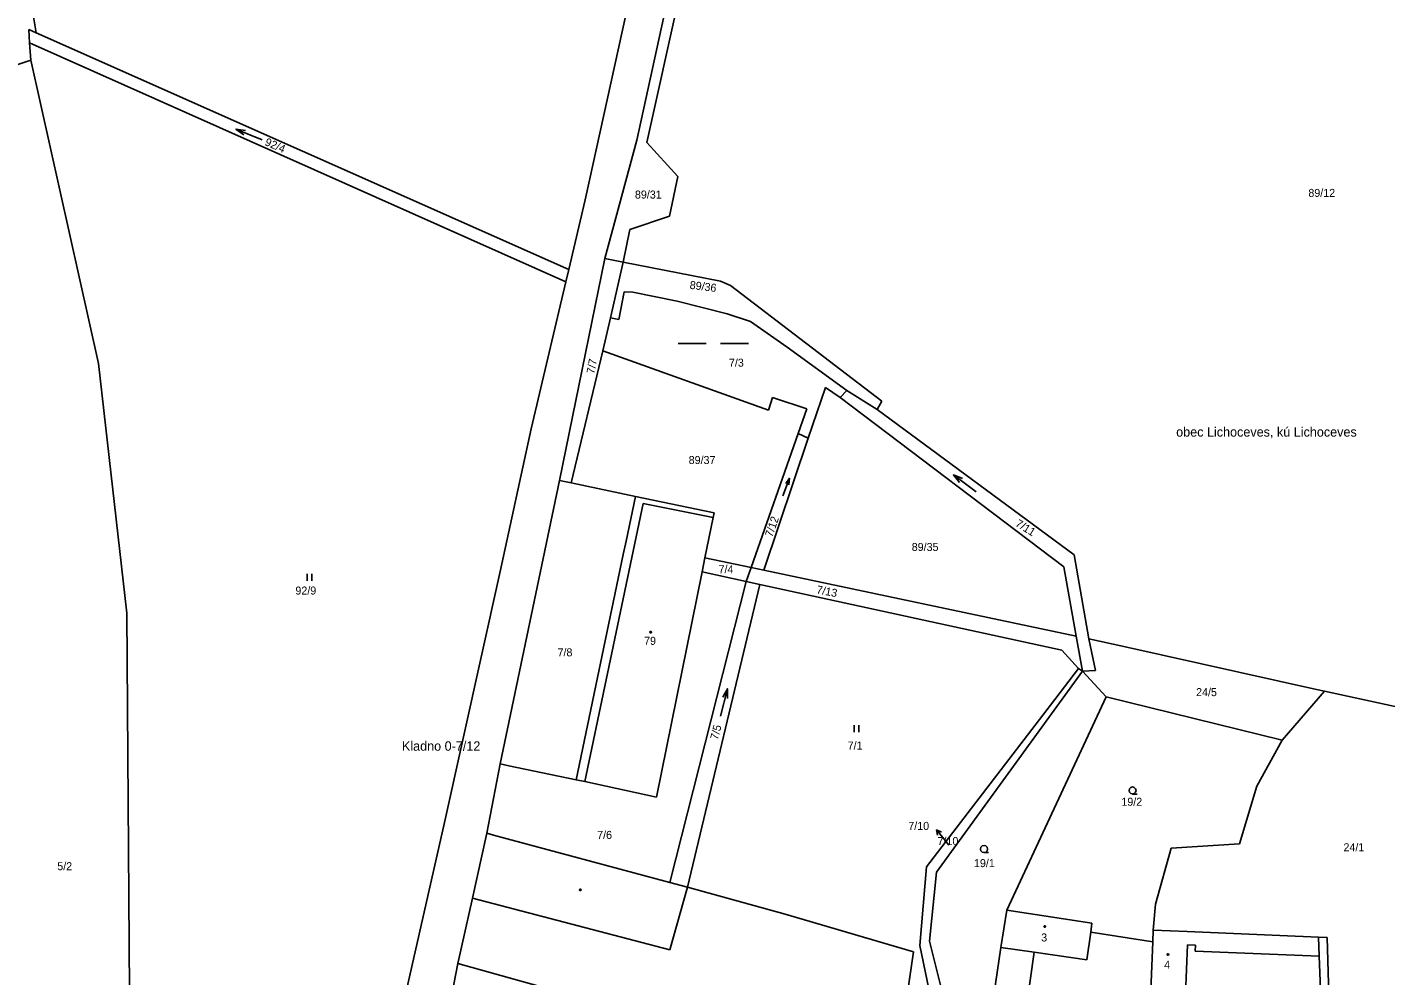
# Model space of a CAD drawing. Extents: x -752500 to -750336, y -1035826 to -1033500.
# Drawn here: x -751692 to -751403.4, y -1034303.4 to -1034101.8 of the extents above; entities that cross this region are included whole.
import ezdxf

# ---------------------------------------------------------------- set-up
doc = ezdxf.new("R2010")
doc.units = 0
for name, color, linetype in [('Default', 7, 'Continuous'), ('Hranice parcel', 7, 'Continuous'), ('ML1000', 7, 'Continuous'), ('Názevy ku_obce_kraje', 7, 'Continuous'), ('Parcelní čísla', 7, 'Continuous'), ('Pop  PČ popisy', 7, 'Continuous'), ('Vnitřní kresba', 7, 'Continuous'), ('Značky budov', 7, 'Continuous'), ('Značky kultur', 7, 'Continuous')]:
    doc.layers.add(name, color=color, linetype=linetype)

# ---------------------------------------------------------------- blocks, each defined once
blk = doc.blocks.new('304')
at = {"layer": 'Default'}
blk.add_lwpolyline([(0, 0), (-0.38, 0.1), (-0.65, 0.37), (-0.75, 0.74), (-0.65, 1.11), (-0.38, 1.38), (-0.01, 1.48), (0.36, 1.38), (0.63, 1.11), (0.73, 0.73), (0.63, 0.35), (0.36, 0.08), (-0.02, -0.02), (0.98, -0.02)], dxfattribs=at)
blk = doc.blocks.new('306')
at = {"layer": 'Default'}
for p, q in [((-0.5, 1.5), (-0.5, 0)), ((0.5, 0), (0.5, 1.5))]:
    blk.add_line(p, q, dxfattribs=at)
blk = doc.blocks.new('802')
at = {"layer": 'Default'}
blk.add_line((-3, 0), (3, 0), dxfattribs=at)
blk.add_lwpolyline([(1, 0.5), (3, 0), (1, -0.5)], dxfattribs=at)
blk = doc.blocks.new('803')
at = {"layer": 'Default'}
for p, q in [((-7.5, 0), (-1.5, 0)), ((1.5, 0), (7.5, 0))]:
    blk.add_line(p, q, dxfattribs=at)
blk = doc.blocks.new('10292')
at = {"layer": 'Default'}
blk.add_line((0, 3), (0, 0), dxfattribs=at)
blk.add_lwpolyline([(-0.5, 2), (0, 3), (0.5, 2)], dxfattribs=at)
blk = doc.blocks.new('402')
at = {"layer": 'Default'}
blk.add_lwpolyline([(0.09, 0.15), (0.18, 0), (0.09, -0.15), (-0.09, -0.15), (-0.18, 0), (-0.09, 0.15), (0.09, 0.15)], dxfattribs=at)

msp = doc.modelspace()

# ---------------------------------------------------------------- linework, layer by layer
at = {"layer": 'Hranice parcel'}
for p, q in [((-751532.72, -1033953.48), (-751573.48, -1034138.53)), ((-751700.05, -1034042.8), (-751690.1, -1034103.01)), ((-751562.48, -1034125.82), (-751545.42, -1034047.4)), ((-751543.07, -1034047.89), (-751560.38, -1034126.29)), ((-751691.65, -1034102.32), (-751691.51, -1034105.14)), ((-751691.65, -1034102.32), (-751690.1, -1034103.01)), ((-751690.1, -1034103.01), (-751576.97, -1034153.3)), ((-751691.51, -1034105.14), (-751577.59, -1034155.94)), ((-751691.51, -1034105.14), (-751691.23, -1034108.8)), ((-751691.23, -1034108.8), (-751714.32, -1034116.59)), ((-751691.23, -1034108.8), (-751676.86, -1034173.28)), ((-751569.32, -1034150.96), (-751562.48, -1034125.82)), ((-751560.38, -1034126.29), (-751553.8, -1034133.55)), ((-751555.58, -1034141.95), (-751553.8, -1034133.55)), ((-751576.97, -1034153.3), (-751573.48, -1034138.53)), ((-751563.96, -1034144.78), (-751555.58, -1034141.95)), ((-751565.42, -1034151.74), (-751563.96, -1034144.78)), ((-751569.32, -1034150.96), (-751578.92, -1034198.1)), ((-751577.59, -1034155.94), (-751576.97, -1034153.3)), ((-751565.42, -1034151.74), (-751569.32, -1034150.96)), ((-751565.42, -1034151.74), (-751568.08, -1034163.6)), ((-751544.76, -1034155.78), (-751565.42, -1034151.74)), ((-751584.95, -1034187.15), (-751577.59, -1034155.94)), ((-751542.62, -1034156.72), (-751544.76, -1034155.78)), ((-751566.32, -1034163.91), (-751565.22, -1034158.05)), ((-751565.22, -1034158.05), (-751563.35, -1034158.13)), ((-751563.35, -1034158.13), (-751553.92, -1034160.04)), ((-751510.47, -1034181.26), (-751542.62, -1034156.72)), ((-751553.92, -1034160.04), (-751543.31, -1034162.73)), ((-751568.08, -1034163.6), (-751569.74, -1034170.56)), ((-751568.08, -1034163.6), (-751566.32, -1034163.91)), ((-751543.31, -1034162.73), (-751538.37, -1034164.38)), ((-751538.37, -1034164.38), (-751530.54, -1034169.81)), ((-751569.74, -1034170.56), (-751576.42, -1034198.63)), ((-751569.74, -1034170.56), (-751534.55, -1034183.21)), ((-751517.91, -1034179.02), (-751530.54, -1034169.81)), ((-751676.86, -1034173.28), (-751670.81, -1034226.35)), ((-751526.08, -1034189.11), (-751522.45, -1034178.34)), ((-751522.45, -1034178.34), (-751519.34, -1034180.51)), ((-751519.34, -1034180.51), (-751517.91, -1034179.02)), ((-751517.91, -1034179.02), (-751511.44, -1034183.03)), ((-751534.55, -1034183.21), (-751533.71, -1034180.48)), ((-751533.71, -1034180.48), (-751526.41, -1034182.89)), ((-751519.34, -1034180.51), (-751471.78, -1034216.49)), ((-751511.44, -1034183.03), (-751510.47, -1034181.26)), ((-751526.41, -1034182.89), (-751528.26, -1034188.18)), ((-751469.64, -1034213.94), (-751511.44, -1034183.03)), ((-751591.5, -1034217.44), (-751584.95, -1034187.15)), ((-751528.26, -1034188.18), (-751538.23, -1034216.63)), ((-751526.08, -1034189.11), (-751528.26, -1034188.18)), ((-751535.54, -1034217.19), (-751526.08, -1034189.11)), ((-751591.53, -1034258.36), (-751578.92, -1034198.1)), ((-751576.42, -1034198.63), (-751578.92, -1034198.1)), ((-751562.81, -1034201.5), (-751576.42, -1034198.63)), ((-751564.8, -1034211.03), (-751562.81, -1034201.5)), ((-751546.11, -1034205.02), (-751562.81, -1034201.5)), ((-751546.31, -1034206.01), (-751546.11, -1034205.02)), ((-751548.04, -1034214.56), (-751546.31, -1034206.01)), ((-751564.8, -1034211.03), (-751565.4, -1034213.88)), ((-751575.38, -1034261.73), (-751565.4, -1034213.88)), ((-751466.49, -1034231.74), (-751469.64, -1034213.94)), ((-751548.04, -1034214.56), (-751548.64, -1034217.53)), ((-751538.23, -1034216.63), (-751548.04, -1034214.56)), ((-751539.29, -1034219.58), (-751538.23, -1034216.63)), ((-751538.23, -1034216.63), (-751535.54, -1034217.19)), ((-751471.78, -1034216.49), (-751469.19, -1034231.17)), ((-751603.35, -1034270.82), (-751591.5, -1034217.44)), ((-751558.35, -1034265.41), (-751548.64, -1034217.53)), ((-751555.46, -1034283.51), (-751539.29, -1034219.58)), ((-751548.64, -1034217.53), (-751539.29, -1034219.58)), ((-751539.29, -1034219.58), (-751536.39, -1034220.21)), ((-751469.19, -1034231.17), (-751535.54, -1034217.19)), ((-751536.39, -1034220.21), (-751551.76, -1034284.51)), ((-751536.39, -1034220.21), (-751472.26, -1034234.2)), ((-751670.81, -1034226.35), (-751670.25, -1034306.59)), ((-751467.87, -1034238.66), (-751469.19, -1034231.17)), ((-751472.26, -1034234.2), (-751468.67, -1034238.05)), ((-751466.49, -1034231.74), (-751465.08, -1034238.47)), ((-751459.05, -1034233.39), (-751466.49, -1034231.74)), ((-751418.12, -1034242.5), (-751459.05, -1034233.39)), ((-751467.87, -1034238.66), (-751498.87, -1034281.35)), ((-751474.66, -1034245.86), (-751468.67, -1034238.05)), ((-751468.67, -1034238.05), (-751467.87, -1034238.66)), ((-751467.87, -1034238.66), (-751465.08, -1034238.47)), ((-751467.87, -1034238.66), (-751462.81, -1034244.11)), ((-751416.41, -1034242.88), (-751425.46, -1034253.3)), ((-751416.41, -1034242.88), (-751418.12, -1034242.5)), ((-751391.16, -1034248.44), (-751416.41, -1034242.88)), ((-751500.99, -1034280.18), (-751474.66, -1034245.86)), ((-751462.81, -1034244.11), (-751483.91, -1034289.38)), ((-751462.81, -1034244.11), (-751425.46, -1034253.3)), ((-751425.46, -1034253.3), (-751430.79, -1034263.05)), ((-751591.53, -1034258.36), (-751594.4, -1034273.07)), ((-751591.53, -1034258.36), (-751589.67, -1034258.75)), ((-751589.67, -1034258.75), (-751575.38, -1034261.73)), ((-751575.38, -1034261.73), (-751573.54, -1034262.11)), ((-751573.54, -1034262.11), (-751558.35, -1034265.41)), ((-751430.79, -1034263.05), (-751434.51, -1034275.3)), ((-751612.23, -1034309.8), (-751603.35, -1034270.82)), ((-751597.39, -1034286.83), (-751594.4, -1034273.07)), ((-751594.4, -1034273.07), (-751592.92, -1034273.47)), ((-751555.46, -1034283.51), (-751592.92, -1034273.47)), ((-751448.98, -1034276.22), (-751452.31, -1034288.17)), ((-751434.51, -1034275.3), (-751448.98, -1034276.22)), ((-751500.99, -1034280.18), (-751502.37, -1034296.89)), ((-751498.87, -1034281.35), (-751500.36, -1034296.01)), ((-751551.76, -1034284.51), (-751555.46, -1034283.51)), ((-751551.76, -1034284.51), (-751531.02, -1034290.29)), ((-751600.51, -1034300.74), (-751597.39, -1034286.83)), ((-751452.31, -1034288.17), (-751452.83, -1034293.68)), ((-751531.02, -1034290.29), (-751503.74, -1034298.26)), ((-751485.15, -1034297.33), (-751483.91, -1034289.38)), ((-751465.83, -1034292.2), (-751483.91, -1034289.38)), ((-751465.83, -1034292.2), (-751466.1, -1034294.09)), ((-751466.1, -1034294.09), (-751452.93, -1034296.13)), ((-751452.93, -1034296.13), (-751452.83, -1034293.68)), ((-751452.83, -1034293.68), (-751445.57, -1034293.97)), ((-751445.57, -1034293.97), (-751417.68, -1034295.13)), ((-751502.37, -1034296.89), (-751498.62, -1034315.07)), ((-751500.36, -1034296.01), (-751495.96, -1034313.45)), ((-751485.15, -1034297.33), (-751488.39, -1034319)), ((-751453.83, -1034319.15), (-751452.93, -1034296.13)), ((-751417.68, -1034295.13), (-751417.55, -1034299.16)), ((-751417.68, -1034295.13), (-751415.84, -1034295.21)), ((-751415.84, -1034295.21), (-751415.11, -1034319.86)), ((-751600.51, -1034300.74), (-751617.27, -1034386.59)), ((-751506.55, -1034317.85), (-751503.74, -1034298.26)), ((-751417.55, -1034299.16), (-751416.76, -1034321.06))]:
    msp.add_line(p, q, dxfattribs=at)
at = {"layer": 'Pop  PČ popisy'}
msp.add_line((-751496.25, -1034275.58), (-751496.96, -1034274.7), dxfattribs=at)
at = {"layer": 'Vnitřní kresba'}
for p, q in [((-751561.19, -1034203.03), (-751573.54, -1034262.11)), ((-751546.31, -1034206.01), (-751561.19, -1034203.03)), ((-751551.76, -1034284.51), (-751555.47, -1034297.82)), ((-751597.39, -1034286.83), (-751555.47, -1034297.82)), ((-751466.95, -1034299.95), (-751466.1, -1034294.09)), ((-751478.09, -1034298.35), (-751485.15, -1034297.33)), ((-751445.52, -1034296.8), (-751445.93, -1034307.23)), ((-751443.84, -1034296.86), (-751445.52, -1034296.8)), ((-751443.89, -1034298.12), (-751443.84, -1034296.86)), ((-751600.51, -1034300.74), (-751527.21, -1034321.17)), ((-751478.09, -1034298.35), (-751481.6, -1034322.73)), ((-751466.95, -1034299.95), (-751478.09, -1034298.35)), ((-751443.89, -1034298.12), (-751417.55, -1034299.16))]:
    msp.add_line(p, q, dxfattribs=at)

# ---------------------------------------------------------------- block references
at = {"layer": 'Pop  PČ popisy', "rotation": 38.789243}
msp.add_blockref('10292', (-751496.96, -1034274.7), dxfattribs=at)
at = {"layer": 'Značky budov'}
for p in [(-751559.56, -1034230.36), (-751574.51, -1034285.11), (-751475.84, -1034292.89), (-751449.68, -1034298.84)]:
    msp.add_blockref('402', p, dxfattribs=at)
at = {"layer": 'Značky kultur'}
for p, rotation in [((-751644.89, -1034124.63), 157.620689), ((-751492.85, -1034198.74), 142.89567399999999), ((-751543.98, -1034245.27), 76.08879499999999)]:
    msp.add_blockref('802', p, dxfattribs=dict(at, rotation=rotation))
for name, p in [('803', (-751546.25, -1034169.05)), ('306', (-751632.04, -1034219.44)), ('306', (-751515.87, -1034251.62)), ('304', (-751457.2, -1034264.72)), ('304', (-751488.75, -1034277.16))]:
    msp.add_blockref(name, p, dxfattribs=at)
at = {"layer": 'Značky kultur', "xscale": 0.6700000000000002, "yscale": 0.6699999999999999, "rotation": 69.614372}
msp.add_blockref('802', (-751530.76, -1034199.53), dxfattribs=at)

# ---------------------------------------------------------------- texts
at = {"layer": 'ML1000'}
msp.add_text('Kladno 0-7/12', height=2, dxfattribs=at).set_placement((-751612.4, -1034255.54))
at = {"layer": 'Názevy ku_obce_kraje'}
msp.add_text('obec Lichoceves, kú Lichoceves', height=2, dxfattribs=at).set_placement((-751447.94, -1034188.81))
at = {"layer": 'Parcelní čísla'}
for s, rotation, p in [('92/4', 336.555, (-751641.68, -1034126.83)), ('89/36', 352.942, (-751551.35, -1034157.39)), ('7/7', 79.412, (-751571.54, -1034175.57)), ('7/12', 70.875, (-751533.74, -1034210.29)), ('7/11', 328.248, (-751482.25, -1034207.71)), ('7/13', 348.874, (-751524.45, -1034222.08)), ('7/5', 75.172, (-751545.31, -1034253.34))]:
    msp.add_text(s, height=1.7, rotation=rotation, dxfattribs=at).set_placement(p)
for s, p in [('89/12', (-751419.86, -1034137.88)), ('89/31', (-751562.91, -1034138.23)), ('7/3', (-751542.94, -1034173.94)), ('89/37', (-751551.49, -1034194.63)), ('89/35', (-751504.11, -1034213.1)), ('7/4', (-751545.14, -1034217.82)), ('92/9', (-751635.03, -1034222.36)), ('79', (-751560.96, -1034233.04)), ('7/8', (-751579.35, -1034235.49)), ('24/5', (-751443.71, -1034243.94)), ('7/1', (-751517.72, -1034255.29)), ('19/2', (-751459.58, -1034267.23)), ('7/10', (-751504.84, -1034272.36)), ('7/6', (-751570.93, -1034274.27)), ('7/10', (-751498.63, -1034275.58)), ('24/1', (-751412.4, -1034276.9)), ('5/2', (-751685.61, -1034280.92)), ('19/1', (-751490.89, -1034280.27)), ('3', (-751476.61, -1034296.06)), ('4', (-751450.5, -1034301.87))]:
    msp.add_text(s, height=1.7, dxfattribs=at).set_placement(p)

doc.saveas('drawing.dxf')
